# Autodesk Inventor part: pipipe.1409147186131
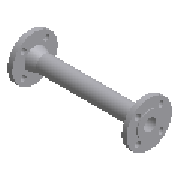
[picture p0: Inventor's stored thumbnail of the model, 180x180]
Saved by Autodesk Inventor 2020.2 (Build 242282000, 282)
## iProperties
Manager: www.cadconsulting.pl
Company: Fabian Stasiak CAD Consulting
IsCustomPart: 1
NAME: PIPING: ISO 2531 Pipe with Integrally Cast Flanges
DATA: <meta><inlinegroups number="1" deflen="50"></inlinegroups><connections number="2"></connections><angles><a>3.14159265358979</a></angles></meta>
Created: 2014-02
Material: Żeliwo sferoidalne
Description: Rury, łączniki, akcesoria z żeliwa sferoidalnego i ich złącza do zastosowań w instalacjach wodnych lub gazowych - Rura odlewana wraz z kołnierzami
Document SubType Name: Modeling
Standard: ISO 2531
Designer: F.Stasiak
Standard Revision: Fifth edition 1998-08-15
Standards Organization: ISO
Language: pl-PL
Size Designation: DN40 PN 10 - 500
Categories: <MemberInstance><Categories><Category DisplayName="Rury cienko- i grubościenne" InternalName="4347fa0f-2144-441d-94cd-e3e15c92b736" Mnemonic="TUBEANDPIPE"><Cate
Stock Number: ISO 2531 Rura odlewana wraz z kołnierzami DN40 PN 10
Density: 7.15 g/cm^3
Appearance: Ciemnoszary
Catalog Web Link: www.expertbooks.pl
L: 1000,000 mm
PL: 1000,000 mm
Author: F.Stasiak
Subject: Zbiór ćwiczeń. Autodesk Inventor 2020. Kurs Professional
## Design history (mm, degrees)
sketch "Sketch1"
  geometry: L1 (0, 0)-(-500, 0); L2 (-500, 0)-(-500, 20); L3 (-951.144, 27)-(-48.856, 27); L4 (-48.856, 27)-(-19, 35); L5 (-19, 35)-(-19, 75); L6 (-19, 75)-(-3, 75); L7 (-3, 75)-(-3, 42); L8 (-3, 42)-(0, 42); L9 (0, 42)-(0, 20); L10 (-1000, 20)-(0, 20); L11 (0, 20)-(0, 0); L12 (-951.144, 27)-(-981, 35); L13 (-981, 35)-(-981, 75); L14 (-981, 75)-(-997, 75); L15 (-997, 75)-(-997, 42); L16 (-997, 42)-(-1000, 42); L17 (-1000, 42)-(-1000, 20); L18 (-1000, 20)-(-1000, 0); 2 further points
  constraints: 36 end point, 9 symmetric about line, 4 parallel, 2 coincident, 2 horizontal, 2 perpendicular, 1 collinear, 1 midpoint, 1 vertical, 7 other
  dimensions: "d0" = 7 distance between parallel lines of L10 L3 (= e); "d2" = 84 diameter of L8 L1 (= d1); "d3" = 3 distance of L7.end L8.end (= f1); "d4" = 19 distance between parallel lines of L9 L5 (= C7); "d5" = 150 diameter of L6 L1 (= D); "d6" = 70 diameter of L4.end L1 (= N3); "d7" = 15 deg angle of L3 L4; "d14" = 1000 distance between parallel lines of L9 L17 (= L); "d15" = 40 diameter of L10 L1 (= ID)
revolve "Revolution1" sketch "Sketch1" stored, may be unused: angle "d10" = 90 deg
sketch "Sketch2"
  geometry: L1 (-55, 0)-(0, 0); L2 (0, 0)-(-38.891, 38.891); C1 r 75 at (0, 0) reference; C2 r 42 at (0, 0) reference; C3 r 9.5 at (-38.891, 38.891); A1 r 55 centre (0, 0) between (-55, 0) and (-38.891, 38.891)
  constraints: 4 end point, 2 centre point, 2 point on circle, 1 coincident, 1 concentric, 1 horizontal
  dimensions: "d8" = 110 diameter of A1 (= K1); "d17" = 19 diameter of C3 (= L2); "d18" = 45 deg angle of L1 L2 (computed from NU)
extrude "Extrusion1" cut sketch "Sketch2" extent not by distance; taper "d9" = 0 deg; stored distance "d13" = 10
pattern_circular "Circular Pattern1" dims angle "d12" = 360 deg
workaxis "Work Axis1"
workpoint "Work Point1"
workaxis "Work Axis2"
workpoint "Work Point2"
body "Solid1"
other parameters: "e" = 7 [user parameter; used in 2 equation terms], "N3" = 70 [user parameter; used in 2 equation terms], "C7" = 19 [user parameter; used in 2 equation terms], "f1" = 3 [user parameter; used in 1 equation term], "d1" = 84 [user parameter; used in 1 equation term], "D" = 150 [user parameter; used in 1 equation term], "K1" = 110 [user parameter; used in 1 equation term], "L2" = 19 [user parameter; used in 1 equation term], "L" = 1000 (= PL) [user parameter; used in 1 equation term], "ID" = 40 [user parameter; used in 2 equation terms], "OD" = 54 [user parameter], "PL" = 1000 [user parameter; used in 1 equation term], "Size_Designation" = 12.345 [user parameter], "PLmin" = 107.21281 (= -7.4641 x e - 3.73205 x ID + 3.73205 x N3 + 2.5 x C7) [user parameter]
